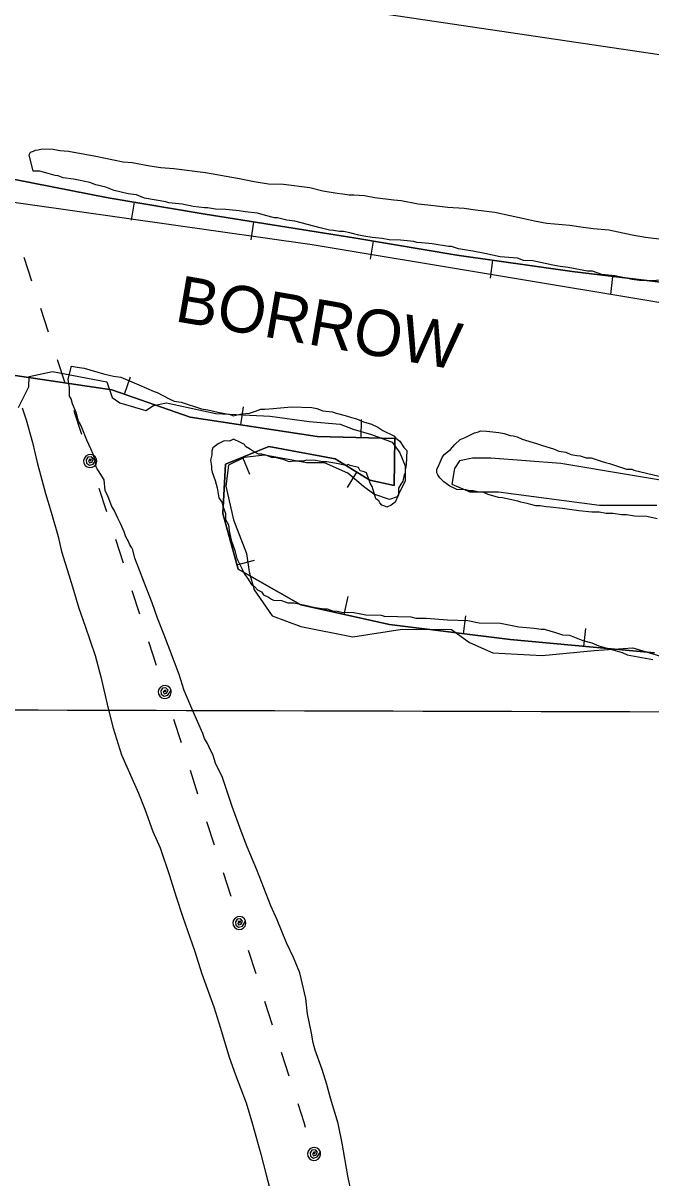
# Model space of a CAD drawing. Extents: x 3172297 to 3210190, y 958463 to 983887.
# Drawn here: x 3180383 to 3181246, y 975391 to 976980 of the extents above; entities that cross this region are included whole.
import ezdxf

# ---------------------------------------------------------------- set-up
doc = ezdxf.new("R2010")
doc.units = 0
for name, color, linetype in [('V-BORW-LINE', 7, 'Continuous'), ('V-GRID-MAJR', 7, 'Continuous'), ('V-RIVR-RANG', 7, 'Continuous'), ('V-SITE-VEGE', 7, 'Continuous'), ('V-TOPO-SHOR', 7, 'Continuous'), ('V-UTIL-LINE', 7, 'Continuous')]:
    doc.layers.add(name, color=color, linetype=linetype)

msp = doc.modelspace()

# ---------------------------------------------------------------- linework, layer by layer
at = {"layer": 'V-BORW-LINE'}
for p, q in [((3180535.3, 976733.9), (3180531.2, 976709.3)), ((3180699.7, 976706.7), (3180695.8, 976682)), ((3180864.2, 976680.3), (3180860.1, 976655.7)), ((3181028.7, 976654.1), (3181025.2, 976629.4)), ((3181193.8, 976631.9), (3181190.8, 976607)), ((3180521.9, 976469.9), (3180530.2, 976493.5)), ((3180682.3, 976427.6), (3180686, 976452.3)), ((3180847.7, 976410.1), (3180848.4, 976435.1)), ((3180684.7, 976383), (3180694.2, 976359.9)), ((3180841.5, 976362.7), (3180828.4, 976341.4)), ((3180676.7, 976234.9), (3180700.8, 976241.5)), ((3180824.5, 976166.8), (3180829.9, 976191.2)), ((3180988.8, 976140.1), (3180991.9, 976164.9)), ((3181154.4, 976122.7), (3181156.7, 976147.6))]:
    msp.add_line(p, q, dxfattribs=at)
for points in [[(3180371.2, 976765), (3180499.5, 976740), (3180633.3, 976717.3), (3180837.5, 976684.8), (3180979.5, 976661.1), (3181138, 976638.6), (3181343.5, 976613.7)], [(3181343.5, 976613.7), (3181138, 976638.6), (3180979.5, 976661.1), (3180837.5, 976684.8), (3180633.3, 976717.3), (3180499.5, 976740), (3180371.2, 976765)], [(3181251.4, 976113.8), (3181052.8, 976132.1), (3180886.8, 976152.9), (3180764.9, 976180.1), (3180678.3, 976229.2), (3180657.4, 976305.7), (3180661, 976373.3), (3180720.7, 976397.9), (3180812.2, 976380.8), (3180859.7, 976351.4), (3180893.1, 976344.2), (3180894.1, 976408.9), (3180787, 976411.8), (3180612.4, 976438), (3180504.7, 976475.9), (3180371.5, 976495.4)], [(3180371.5, 976495.4), (3180504.7, 976475.9), (3180612.4, 976438), (3180787, 976411.8), (3180894.1, 976408.9), (3180893.1, 976344.2), (3180859.7, 976351.4), (3180812.2, 976380.8), (3180720.7, 976397.9), (3180661, 976373.3), (3180657.4, 976305.7), (3180678.3, 976229.2), (3180764.9, 976180.1), (3180886.8, 976152.9), (3181052.8, 976132.1), (3181251.4, 976113.8)]]:
    msp.add_lwpolyline(points, dxfattribs=at)
at = {"layer": 'V-GRID-MAJR'}
msp.add_spline([(3176574.9, 976046.2), (3181787.8, 976031.4), (3187000.7, 976017.3), (3192213.6, 976004.1), (3197426.5, 975991.6), (3202639.4, 975979.8), (3207852.4, 975968.8)], degree=3, dxfattribs=at)
at = {"layer": 'V-SITE-VEGE'}
for p, q in [((3180381.5, 976451), (3180387, 976434.4)), ((3180387, 976434.4), (3180395.5, 976403.1)), ((3180395.5, 976403.1), (3180402.1, 976375.8)), ((3180402.1, 976375.8), (3180413.6, 976333.2)), ((3180413.6, 976333.2), (3180421, 976307.3)), ((3180421, 976307.3), (3180430.7, 976274)), ((3180430.7, 976274), (3180435.5, 976253.3)), ((3180435.5, 976253.3), (3180445.3, 976221.4)), ((3180445.3, 976221.4), (3180452.1, 976200)), ((3180452.1, 976200), (3180459.4, 976175.4)), ((3180459.4, 976175.4), (3180468.1, 976150.7)), ((3180468.1, 976150.7), (3180481.6, 976110.1)), ((3180481.6, 976110.1), (3180489.5, 976080.8)), ((3180489.5, 976080.8), (3180499.7, 976037.5)), ((3180499.7, 976037.5), (3180506.3, 976010.3)), ((3180506.3, 976010.3), (3180518, 975973.6)), ((3180518, 975973.6), (3180541.2, 975920.8)), ((3180541.2, 975920.8), (3180549.9, 975898.8)), ((3180549.9, 975898.8), (3180561.1, 975868.1)), ((3180561.1, 975868.1), (3180571.1, 975845.4)), ((3180571.1, 975845.4), (3180583.5, 975808.7)), ((3180583.5, 975808.7), (3180592.7, 975779.4)), ((3180592.7, 975779.4), (3180602.5, 975750.1)), ((3180602.5, 975750.1), (3180618.6, 975704.1)), ((3180618.6, 975704.1), (3180628.4, 975672.1)), ((3180628.4, 975672.1), (3180645.2, 975626.7)), ((3180645.2, 975626.7), (3180654.4, 975597.4)), ((3180654.4, 975597.4), (3180666, 975557.4)), ((3180666, 975557.4), (3180674.7, 975533.4)), ((3180674.7, 975533.4), (3180689.6, 975494.7)), ((3180689.6, 975494.7), (3180698.1, 975465.4)), ((3180698.1, 975465.4), (3180709.7, 975424.1)), ((3180709.7, 975424.1), (3180717, 975395.5)), ((3180717, 975395.5), (3180729.1, 975350.3))]:
    msp.add_line(p, q, dxfattribs=at)
for points in [[(3181286.8, 976627.5), (3181243.2, 976625.8), (3181230.6, 976626.1), (3181220.8, 976627.7), (3181197, 976632.5), (3181178.8, 976634.3), (3181166.3, 976638.9), (3181159.3, 976639), (3181132.7, 976643.9), (3181121.5, 976645.6), (3181111.7, 976647.2), (3181083.8, 976653.5), (3181071.2, 976653.8), (3181062.8, 976656.8), (3181039, 976658.8), (3181018.1, 976663.5), (3181001.3, 976666.7), (3180990.1, 976668.4), (3180981.7, 976670), (3180972, 976673), (3180967.8, 976673.2), (3180945.4, 976676.5), (3180931.4, 976678.2), (3180924.4, 976678.4), (3180920.2, 976679.9), (3180902, 976681.8), (3180886.5, 976682.1), (3180876.7, 976683.8), (3180862.7, 976685.5), (3180851.6, 976687.2), (3180844.6, 976688.8), (3180832, 976691.9), (3180823.6, 976693.5), (3180818, 976693.6), (3180809.6, 976695.2), (3180804, 976695.4), (3180791.5, 976698.5), (3180756.6, 976707.7), (3180745.4, 976709.4), (3180732.8, 976712.5), (3180728.6, 976712.6), (3180716.1, 976715.7), (3180704.9, 976718.8), (3180688.1, 976720.6), (3180679.7, 976722.2), (3180661.5, 976724.1), (3180647.5, 976724.4), (3180636.3, 976726.1), (3180632.1, 976726.2), (3180616.7, 976728), (3180601.3, 976731.2), (3180583.1, 976733), (3180578.9, 976734.5), (3180549.5, 976739.4), (3180538.4, 976743.9), (3180527.2, 976745.6), (3180507.7, 976750.3), (3180496.6, 976754.7), (3180482.6, 976757.9), (3180474.2, 976760.9), (3180451.9, 976765.7), (3180437.9, 976767.4), (3180430.9, 976770.4), (3180426.7, 976770.5), (3180417, 976773.5), (3180405.8, 976776.6), (3180396.4, 976776.8), (3180390.8, 976799.1), (3180392.9, 976803), (3180396.9, 976804.2), (3180399.5, 976805.5), (3180403.5, 976806.1), (3180408.8, 976807.2), (3180424, 976806.9), (3180430.6, 976805.4), (3180433.2, 976805.3), (3180445.1, 976804.4), (3180482.6, 976797.5), (3180495.8, 976794.6), (3180507, 976792.3), (3180520.1, 976789.3), (3180532.7, 976788.4), (3180557, 976783.8), (3180572.2, 976781.5), (3180590, 976780.4), (3180633.5, 976774.7), (3180677.6, 976767), (3180700.7, 976762.5), (3180720.4, 976759.4), (3180740.9, 976758.9), (3180777.2, 976754), (3180794.9, 976749.6), (3180814.7, 976746.5)], [(3180814.7, 976746.5), (3180822.6, 976745.7), (3180831.1, 976744.1), (3180837.8, 976744), (3180852.3, 976743), (3180866.8, 976740.6), (3180892.5, 976737.4), (3180903, 976736.4), (3180926.1, 976731.9), (3180939.3, 976730.3), (3180955.7, 976728.6), (3180966.9, 976727), (3180989.4, 976725.8), (3181005.2, 976723.4), (3181031.6, 976720.1), (3181073.7, 976711.2), (3181086.2, 976708.2), (3181103.3, 976705.2), (3181135, 976702.4), (3181150.1, 976700.1), (3181167.2, 976697.7), (3181188.4, 976695.8), (3181220.6, 976689.1), (3181239, 976686), (3181265.4, 976682.7)], [(3180499.5, 976328.5), (3180495.7, 976337.2), (3180494.1, 976351.8), (3180486.5, 976364.5), (3180484.6, 976367.2), (3180483.3, 976369.9), (3180482.1, 976375.9), (3180479.1, 976387.2), (3180476, 976394.5), (3180470.3, 976406.6), (3180463.4, 976423.9), (3180461.6, 976427.9), (3180459, 976432.6), (3180457.8, 976436), (3180455.4, 976444.6), (3180450.4, 976456.6), (3180448.5, 976463.3), (3180446.6, 976467.3), (3180446.3, 976478.6), (3180444.6, 976490.5), (3180449.1, 976508.4), (3180456.9, 976507.2), (3180466.7, 976505.6), (3180493.2, 976497.9), (3180507.1, 976494.7), (3180516.9, 976493.1), (3180541.9, 976482.7), (3180562.8, 976473.7), (3180567, 976472.2), (3180583.6, 976463.4), (3180590.5, 976460.4), (3180600.3, 976458.8), (3180628.2, 976449.7), (3180636.6, 976448.1), (3180650.5, 976444.9), (3180667.3, 976441.7), (3180671.5, 976440.2), (3180677.1, 976441.5), (3180684.2, 976442.7), (3180694, 976443.9), (3180702.5, 976446.5), (3180709.6, 976449.1), (3180715.2, 976449), (3180726.5, 976450.1), (3180751.8, 976452.3), (3180779.9, 976451.6), (3180786.9, 976450.1), (3180795.2, 976447.1), (3180807.8, 976445.4), (3180813.4, 976443.8), (3180825.9, 976440.7), (3180834.3, 976437.7), (3180841.3, 976436.1), (3180851, 976431.7), (3180862.1, 976428.6), (3180870.5, 976424.2), (3180877.4, 976419.8), (3180892.6, 976412.4), (3180895.4, 976409.5), (3180900.9, 976405.2), (3180906.3, 976396.6), (3180910.4, 976392.3), (3180909.9, 976372.7), (3180908.4, 976365.7), (3180908.3, 976361.5), (3180906.8, 976358.7), (3180905.2, 976350.3), (3180902.3, 976346.2), (3180899.3, 976340.6), (3180899.1, 976330.8), (3180896.2, 976325.3), (3180894.7, 976321.1), (3180888.9, 976317), (3180883.3, 976314.4), (3180880.5, 976315.8), (3180876.3, 976317.3), (3180873.6, 976320.2), (3180872.2, 976323), (3180868.1, 976326), (3180862.9, 976342.9), (3180860.2, 976347.2), (3180854.9, 976361.4), (3180852.1, 976362.8), (3180846.6, 976364.4), (3180843.9, 976368.7), (3180832.7, 976371.7), (3180829.9, 976373.2), (3180827.1, 976371.9), (3180811.7, 976375.1), (3180800.5, 976376.7), (3180794.9, 976376.9), (3180785.1, 976378.5), (3180772.5, 976378.8), (3180768.2, 976377.5), (3180755.6, 976377.8), (3180748.6, 976376.6), (3180741.6, 976379.6), (3180729.1, 976382.7), (3180724.9, 976382.8), (3180716.5, 976385.8), (3180710.9, 976387.3)], [(3180959.3, 976382.7), (3180962.2, 976386.9), (3180970.8, 976393.7), (3180976.6, 976400.6), (3180983.8, 976407.4), (3180990.9, 976410), (3180998, 976414.1), (3181003.7, 976416.7), (3181009.3, 976418), (3181012.2, 976419.3), (3181020.6, 976419.1), (3181037.4, 976417.3), (3181044.4, 976415.8), (3181052.7, 976412.8), (3181056.9, 976412.6), (3181062.5, 976411.1), (3181069.5, 976408.1), (3181089, 976402), (3181097.3, 976399), (3181112.6, 976394.5), (3181119.6, 976391.5), (3181129.4, 976389.8), (3181136.3, 976386.9), (3181144.7, 976385.3), (3181148.9, 976385.2), (3181157.3, 976382.1), (3181164.3, 976382), (3181179.6, 976377.4), (3181183.8, 976375.9), (3181189.4, 976374.3), (3181199.1, 976371.3), (3181213.1, 976366.8), (3181220.1, 976366.6), (3181222.9, 976365.1), (3181257.8, 976357.2)], [(3180710.9, 976387.3), (3180706.7, 976387.4), (3180698.4, 976391.8), (3180694.2, 976394.7), (3180688.7, 976397.7), (3180687.4, 976400.5), (3180679.1, 976404.9), (3180674.9, 976406.4), (3180672.1, 976407.9), (3180666.4, 976405.2), (3180659.4, 976405.4), (3180650.9, 976401.4), (3180643.7, 976396), (3180642.2, 976391.8), (3180642.1, 976386.2), (3180640.5, 976379.2), (3180641.7, 976370.7), (3180641.6, 976366.5), (3180642.9, 976362.3), (3180646.9, 976351), (3180649.4, 976341.1), (3180651.9, 976327), (3180656, 976321.3), (3180657.2, 976315.6), (3180661.2, 976305.7), (3180661, 976297.3), (3180665, 976290.1), (3180666.2, 976281.7), (3180668.7, 976269), (3180674, 976254.8), (3180676.6, 976243.5), (3180684.6, 976227.9), (3180687.3, 976222.2), (3180691.3, 976216.5), (3180696.8, 976207.9), (3180700.9, 976205), (3180705, 976200.7), (3180710.5, 976197.8), (3180713.3, 976193.5), (3180720.2, 976190.5), (3180724.3, 976187.6), (3180727.1, 976186.2), (3180738.3, 976185.9), (3180746.7, 976182.9), (3180755.1, 976182.7), (3180770.5, 976179.5), (3180784.4, 976176.3), (3180797, 976174.6), (3180801.2, 976174.5), (3180808.2, 976171.6), (3180815.2, 976171.4), (3180820.8, 976169.8), (3180837.6, 976169.4), (3180847.4, 976167.8), (3180854.4, 976166.2), (3180875.4, 976165.7), (3180879.6, 976164.2), (3180916.1, 976163.3), (3180923.1, 976161.8), (3180937.1, 976161.4), (3180966.6, 976159.3), (3180994.6, 976158.6), (3181010, 976155.4), (3181039.5, 976154.7), (3181064.6, 976149.9), (3181085.6, 976148), (3181095.4, 976146.4), (3181099.6, 976146.3), (3181115, 976141.7), (3181124.7, 976138.6), (3181134.5, 976138.4), (3181141.5, 976135.4), (3181152.6, 976130.9), (3181165.2, 976127.8), (3181174.9, 976123.4), (3181207, 976114.2), (3181213.9, 976111.2), (3181248.9, 976104.7)], [(3181254.9, 976298.3), (3181241, 976301.5), (3181224.1, 976301.9), (3181212.9, 976303.6), (3181205.9, 976303.7), (3181194.7, 976305.4), (3181184.9, 976305.7), (3181175.1, 976307.3), (3181165.3, 976307.5), (3181147.1, 976309.4), (3181134.5, 976311.1), (3181124.7, 976312.7), (3181107.9, 976314.5), (3181102.3, 976314.7), (3181093.9, 976316.3), (3181088.3, 976316.4), (3181081.3, 976318), (3181075.7, 976319.5), (3181067.3, 976321.1), (3181063.2, 976322.6), (3181042.2, 976327.4), (3181036.6, 976327.5), (3181022.7, 976332), (3181015.7, 976335), (3181010.1, 976335.2), (3181001.7, 976336.8), (3180997.5, 976336.9), (3180992, 976338.4), (3180979.3, 976338.7), (3180976.5, 976340.2), (3180969.6, 976343.2), (3180961.3, 976349), (3180955.8, 976354.7), (3180953.1, 976359), (3180951.8, 976361.8), (3180951.9, 976366), (3180954.9, 976373), (3180959.3, 976382.7)], [(3180835.8, 975362.9), (3180829.3, 975394.1), (3180821.8, 975439.3), (3180815.9, 975466.5), (3180805.5, 975501.2), (3180800.6, 975519.8), (3180793.9, 975540.5), (3180784.6, 975567.1), (3180781.5, 975577.1), (3180779.2, 975590.4), (3180773.9, 975617), (3180771.8, 975638.2), (3180763.4, 975673.4), (3180754.6, 975694.8), (3180745.2, 975714.9), (3180732.1, 975746.3), (3180723.3, 975765.7), (3180704, 975815.1), (3180690.8, 975847.1), (3180682.8, 975868.5), (3180670.4, 975902.5), (3180663.6, 975923.2), (3180656.8, 975942.5), (3180647.3, 975961.9), (3180644.3, 975972.6), (3180638.6, 975983.9), (3180636.1, 975989.3), (3180632.3, 975996), (3180629.8, 976002.7), (3180622.9, 976018.7), (3180616, 976034.1), (3180604.1, 976062.1), (3180597.4, 976084.1), (3180584.3, 976118.2), (3180576.3, 976139.5), (3180567.5, 976161.5), (3180560.1, 976182.9), (3180548.9, 976212.2), (3180542.7, 976227.6), (3180536.5, 976244.3), (3180533.4, 976255.6), (3180532.2, 976258.3), (3180529.6, 976262.3), (3180527.8, 976267), (3180524, 976273.7), (3180521.5, 976280.4), (3180516.5, 976291.7), (3180512.7, 976299.1), (3180507.7, 976310.4), (3180504.5, 976315.2), (3180499.5, 976328.5)]]:
    msp.add_lwpolyline(points, dxfattribs=at)
at = {"layer": 'V-TOPO-SHOR'}
for points in [[(3180653.6, 977027.3), (3181397.9, 976916.5), (3181904.8, 976852.8), (3182215.4, 976816.3)], [(3181762, 976512.1), (3180780.4, 976675.2), (3180191.4, 976758.8)], [(3180376.3, 976451.3), (3180390.6, 976479.8), (3180390.7, 976494.1), (3180422.8, 976501.1), (3180497.8, 976486.7), (3180504.9, 976465.2), (3180515.6, 976458.1), (3180551.3, 976447.3), (3180562, 976454.4), (3180579.9, 976457.9), (3180647.7, 976443.4), (3180722.7, 976439.7), (3180776.2, 976432.4), (3180819, 976428.7), (3180836.9, 976421.6), (3180861.9, 976414.3), (3180890.4, 976403.6), (3180901.1, 976389.3), (3180908.2, 976371.4), (3180908.1, 976350), (3180897.4, 976328.6), (3180886.6, 976325), (3180865.2, 976332.2), (3180851, 976343), (3180829.6, 976360.9), (3180797.5, 976375.2), (3180772.5, 976375.3), (3180715.4, 976386.1), (3180686.8, 976382.6), (3180665.3, 976372), (3180661.7, 976343.4), (3180672.3, 976297), (3180690, 976250.5), (3180693.6, 976225.5), (3180700.6, 976200.5), (3180725.5, 976164.7), (3180764.8, 976150.3), (3180836.2, 976135.9), (3180904, 976146.4), (3180971.9, 976146.2), (3180996.9, 976128.3), (3181029, 976114), (3181096.8, 976110.2), (3181168.2, 976117.2), (3181221.8, 976120.6), (3181282.5, 976102.6)], [(3181404.4, 976327.3), (3181122.4, 976374.4), (3181026, 976381.8), (3181001, 976381.9), (3180983.2, 976378.3), (3180976, 976367.6), (3180972.4, 976346.2), (3180997.4, 976335.4), (3181036.6, 976335.4), (3181175.9, 976317.2), (3181254.4, 976317)]]:
    msp.add_lwpolyline(points, dxfattribs=at)
at = {"layer": 'V-UTIL-LINE'}
for points in [[(3180383.7, 976658.3), (3180394.2, 976626)], [(3180406.6, 976588), (3180417.1, 976555.6)], [(3180429.5, 976517.6), (3180440.1, 976485.3)], [(3180452.5, 976447.3), (3180453, 976445.6), (3180462.9, 976414.9)], [(3180474.9, 976377.8), (3180476.7, 976380.1), (3180474.3, 976380.2), (3180472.7, 976377.9), (3180473.9, 976375.3), (3180477.2, 976376.2), (3180479.4, 976380.3), (3180476.6, 976383.4), (3180471.7, 976383.2), (3180469.4, 976379.3), (3180469.8, 976374.8), (3180473.9, 976372.2), (3180479.2, 976373.6), (3180483.5, 976380.5), (3180481.8, 976383.6), (3180479, 976385.8), (3180475.6, 976386.8), (3180472.1, 976386.3), (3180469.1, 976384.6), (3180466.9, 976381.9), (3180465.9, 976378.5), (3180466.3, 976375), (3180468.1, 976371.9), (3180470.8, 976369.8), (3180474.2, 976368.8), (3180477.7, 976369.2), (3180480.7, 976370.9), (3180482.9, 976373.7), (3180483.9, 976377.1), (3180483.5, 976380.5)], [(3180486.9, 976340.7), (3180497.3, 976308.3)], [(3180509.6, 976270.3), (3180520.1, 976237.9)], [(3180532.4, 976199.8), (3180542.8, 976167.5)], [(3180555.1, 976129.4), (3180565.6, 976097.1)], [(3180577.6, 976059.9), (3180579.3, 976062.2), (3180577, 976062.3), (3180575.4, 976060.1), (3180576.6, 976057.4), (3180579.9, 976058.3), (3180582.1, 976062.4), (3180579.2, 976065.6), (3180574.3, 976065.4), (3180572.1, 976061.4), (3180572.5, 976057), (3180576.5, 976054.4), (3180581.9, 976055.8), (3180586.1, 976062.7), (3180584.4, 976065.8), (3180581.7, 976068), (3180578.3, 976068.9), (3180574.8, 976068.5), (3180571.7, 976066.8), (3180569.5, 976064), (3180568.6, 976060.7), (3180569, 976057.2), (3180570.7, 976054.1), (3180573.5, 976051.9), (3180576.8, 976051), (3180580.3, 976051.4), (3180583.4, 976053.1), (3180585.6, 976055.8), (3180586.5, 976059.2), (3180586.1, 976062.7)], [(3180589.5, 976022.8), (3180600, 975990.5)], [(3180612.3, 975952.4), (3180622.7, 975920.1)], [(3180635, 975882), (3180645.5, 975849.7)], [(3180657.8, 975811.6), (3180668.2, 975779.2)], [(3180680.2, 975742.1), (3180682, 975744.4), (3180679.6, 975744.5), (3180678, 975742.3), (3180679.2, 975739.6), (3180682.5, 975740.5), (3180684.7, 975744.6), (3180681.9, 975747.8), (3180677, 975747.5), (3180674.7, 975743.6), (3180675.1, 975739.1), (3180679.2, 975736.5), (3180684.5, 975737.9), (3180688.8, 975744.9), (3180687.1, 975747.9), (3180684.3, 975750.1), (3180680.9, 975751.1), (3180677.4, 975750.7), (3180674.4, 975749), (3180672.2, 975746.2), (3180671.2, 975742.8), (3180671.6, 975739.3), (3180673.4, 975736.3), (3180676.1, 975734.1), (3180679.5, 975733.1), (3180683, 975733.5), (3180686, 975735.3), (3180688.2, 975738), (3180689.2, 975741.4), (3180688.8, 975744.9)], [(3180692.2, 975705), (3180702.6, 975672.7)], [(3180714.9, 975634.6), (3180725.4, 975602.2)], [(3180737.7, 975564.2), (3180748.1, 975531.8)], [(3180760.4, 975493.8), (3180768.7, 975468), (3180770.9, 975461.4)], [(3180783.1, 975424.3), (3180784.8, 975426.6), (3180782.5, 975426.7), (3180780.9, 975424.5), (3180782.1, 975421.8), (3180785.4, 975422.7), (3180787.6, 975426.9), (3180784.7, 975430), (3180779.8, 975429.8), (3180777.6, 975425.8), (3180778, 975421.3), (3180782.1, 975418.8), (3180787.4, 975420.2), (3180791.6, 975427.1), (3180789.9, 975430.2), (3180787.1, 975432.4), (3180783.7, 975433.3), (3180780.3, 975432.9), (3180777.2, 975431.2), (3180775, 975428.4), (3180774.1, 975425), (3180774.5, 975421.5), (3180776.2, 975418.5), (3180779, 975416.3), (3180782.4, 975415.4), (3180785.9, 975415.8), (3180788.9, 975417.5), (3180791.1, 975420.3), (3180792, 975423.7), (3180791.6, 975427.1)]]:
    msp.add_lwpolyline(points, dxfattribs=at)

# ---------------------------------------------------------------- texts
at = {"layer": 'V-RIVR-RANG'}
msp.add_text('BORROW', height=64, rotation=350.1747, dxfattribs=at).set_placement((3180589.8, 976570.5))

doc.saveas('drawing.dxf')
